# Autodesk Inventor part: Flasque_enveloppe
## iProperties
Shininess: 64.0
Length Units: 11269
Angle Units: 11279
Time Units: 11290
Mass Units: 11283
Length Display Precision: 3
Angle Display Precision: 2
Compacted: True
Part Number: Flasque_enveloppe
Document SubType Name: Modeling
Created: 2008-02
Material: Par défaut
Designer: Pascal
Density: 0.0
Volumn: 0.0
Area: 0.0
PropertySet Name: Model Information
Control State: 0
Master: False
Checked Out: False
DESIGNATION: Flasque enveloppe
Author: Pascal
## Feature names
1. Extrusion1
